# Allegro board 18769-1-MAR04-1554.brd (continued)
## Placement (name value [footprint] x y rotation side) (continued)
FC8970  SC12P50V2JN-DL-GP  [C402H22]  102.27 33.18 270 top
FC8971  SC12P50V2JN-DL-GP  [C402H22]  93.4 36.25 0 top
FC8972  SC12P50V2JN-DL-GP  [C402H22]  42.92 29.56 315 top
FC8973  SC12P50V2JN-DL-GP  [C402H22]  43.49 29.03 315 top
FP1  PTWO-CON8-11-GP  [FH52-8S-D5SH]  140.6 6.1 180 bottom
FSW1  SW-SLIDE3P-11-GP  [MSS3-Q-T-R]  172.66 24.46 270 top
G1801  GAP-OPEN  [CON2O-U]  117.2 28.58 0 top
GPU1  N17S-G1-A1-GP  [BGA595M23H83]  156.98 63.76 45 bottom
H5  HOLE233R142-GP-U1  [HOLE233R142]  7.8 44.5 0 top
H9  HOLE233R142-GP-U1  [HOLE233R142]  57.92 67.31 180 bottom
H10  HOLE233R142-GP-U1  [HOLE233R142]  57.92 43.01 180 bottom
H11  HOLE233R142-GP-U1  [HOLE233R142]  118.92 43.01 180 bottom
H12  HOLE233R142-GP-U1  [HOLE233R142]  118.92 67.31 180 bottom
H13  HOLE276R150-GP  [HOLE276R150]  138.13 68.48 0 bottom
H14  HOLE276R150-GP  [HOLE276R150]  166.74 43.33 180 bottom
H15  HOLE276R150-GP  [HOLE276R150]  166.04 79.47 180 bottom
H20  HOLE233R142-GP-U1  [HOLE233R142]  6.8 23.1 180 bottom
H22  HOLET237B213R142-GP  [HOLET237B213R142]  153.6 6.77 0 top
HALL1  AH9247-W-7-GP  [SOT23-2D8-312H56]  2.15 49.15 180 top
HDMI1  SKT-HDMI23-133-GP-U  [SKT-HDMI23-178125-2]  4.25 59.1 90 bottom
HS1  STFT237B158R128H48-GP  [STFT237B158R128H48]  193.44 22.05 180 bottom
HS2  STFT237B158R128H48-GP  [STFT237B158R128H48]  39.09 25.14 180 bottom
IO1  STM-CON30-6-GP  [20455-030E-12]  179.6 6 180 bottom
IO2  HRS-CONN40D-7-GP  [DF40C-40DP-D4V-51]  194.6 5.1 270 bottom
KB1  ACES-CON30-29-GP  [50699-03001-W01]  50.3 5.1 180 bottom
KBBL1  ACES-CON4-90-GP-U  [50698-00401-W01-U]  27.06 4.78 180 bottom
L7801  MHC1608S300QBP-GP  [L603H38]  159.99 67.96 229 top
L7901  MHC1608S300QBP-GP  [L603H38]  151.65 61.94 45 top
LCD1  IPEX-CON40-8-GP  [20879-040E-01]  46.6 81.1 0 bottom
LED1  LED-YW-5-GP  [LED3020-3P-19H44]  4 71.27 0 top
NOREF  -  []  39.4 81.73 0 top
NOREF#2  -  []  67.84 44 90 top
NOREF#3  -  []  138.11 89.19 0 top
NOREF#4  -  []  39.4 81.73 0 top
NOREF#5  -  []  20.55 45.33 90 top
NOREF#6  -  []  65.06 20.07 90 top
NOREF#7  -  []  76.26 30.37 0 top
NOREF#8  -  []  39.4 81.73 0 top
NOREF#9  -  []  14.85 8.28 0 top
NOREF#10  -  []  -166.49 -397.79 0 top
NOREF#11  -  []  39.09 22.63 90 top
NOREF#12  -  []  37.06 81.1 90 top
NOREF#13  -  []  -1.16 39.32 0 top
NOREF#14  -  []  38.8 78.82 0 top
NOREF#15  -  []  37.06 81.1 0 top
NOREF#16  -  [unnamed#2]  191.06 101.55 180 top
NOREF#17  -  []  65.06 29.67 0 top
NOREF#18  -  []  14.85 -1.52 90 top
NOREF#19  -  []  103.16 24.07 90 top
NOREF#20  -  []  56.49 82.12 90 top
NOREF#21  -  []  37.06 81.1 90 top
NOREF#22  -  []  103.16 20.07 90 top
NOREF#23  -  []  102 8.07 0 top
NOREF#24  -  []  18.84 44.83 0 top
NOREF#25  -  []  83.61 82.77 0 top
NOREF#26  -  []  174.54 74.78 0 top
NOREF#27  -  []  65.06 24.07 90 top
NOREF#28  -  []  204 81.94 0 top
NOREF#29  -  []  137.29 69.3 90 top
NOREF#30  -  []  38.8 78.82 0 top
NOREF#31  -  []  39.09 22.63 90 top
NOREF#32  -  []  39.4 78.07 0 top
NOREF#33  -  []  83.98 29.67 0 top
NOREF#34  -  []  196.47 10.12 90 top
NOREF#35  -  []  39.4 78.07 0 top
NOREF#36  *  [unnamed#2]  175.07 38.34 0 top
NOREF#37  *  [unnamed#2]  0.25 123.71 0 top
NOREF#38  -  []  37.01 78.74 90 top
NOREF#39  -  []  37.01 78.74 0 top
NOREF#40  -  []  38.16 81.73 0 top
NOREF#41  -  []  6.66 2.17 0 top
NOREF#42  -  []  18.84 44.83 0 top
NOREF#43  -  []  94.93 19.37 90 top
NOREF#44  -  []  115.2 68.26 90 top
NOREF#45  -  []  -0.83 28.22 0 top
NOREF#46  -  []  39.4 81.73 0 top
NOREF#47  -  []  37.06 81.1 0 top
NOREF#48  -  []  16.17 9.09 0 top
NOREF#49  -  []  114.39 99.23 180 top
NOREF#50  -  []  37.01 78.74 90 top
NOREF#51  -  []  37.06 81.1 0 top
NOREF#52  -  []  19.6 47.46 0 top
NOREF#53  -  []  193.2 1.3 0 top
NOREF#54  -  []  121.19 117.8 0 top
NOREF#55  -  []  38.8 78.82 0 top
NOREF#56  -  []  56.49 82.12 90 top
NOREF#57  -  []  45.93 27.81 90 top
NOREF#58  -  []  115.74 112.35 0 top
NOREF#59  -  []  67.84 43.35 0 top
NOREF#60  -  []  -2.81 37.24 0 top
NOREF#61  *  [unnamed#2]  163.12 86.33 0 top
NOREF#62  -  []  74.81 29.67 0 top
NOREF#63  -  []  38.16 81.73 0 top
NOREF#64  -  []  39.4 78.07 0 top
NOREF#65  -  []  101.34 19.89 0 top
NOREF#66  -  []  18.84 44.83 0 top
NOREF#67  -  []  39.83 5.94 90 top
NOREF#68  -  []  16.46 -2.32 90 top
NOREF#69  -  []  39.83 15.62 0 top
NOREF#70  -  []  65.06 23.27 90 top
NOREF#71  -  []  45.93 23.81 90 top
NOREF#72  -  []  18.84 44.83 90 top
NOREF#73  -  []  38.8 78.82 0 top
NOREF#74  -  []  83.98 23.27 90 top
NOREF#75  -  []  32.64 23.12 90 top
NOREF#76  -  []  137.29 68.8 90 top
NOREF#77  -  []  56.49 82.12 90 top
NOREF#78  -  []  38.09 78.07 0 top
NOREF#79  -  []  93.73 29.67 0 top
NOREF#80  -  []  39.4 78.07 0 top
NOREF#81  -  []  83.98 20.07 90 top
NOREF#82  -  [unnamed#2]  -3.68 12.32 0 top
NOREF#83  -  []  150.59 7.02 0 top
NOREF#84  *  [unnamed#2]  130.2 80.68 0 top
NOREF#85  -  []  188.8 52.8 0 top
NOREF#86  -  []  3.03 27.02 90 top
NOREF#87  -  []  81.95 42.9 90 top
NOREF#88  -  []  39.4 81.73 0 top
NOREF#89  -  []  45.52 5.94 90 top
NOREF#90  -  []  36.71 86.46 0 top
NOREF#91  -  []  38.8 78.82 90 top
NOREF#92  -  []  38.8 78.82 0 top
NOREF#93  *  [unnamed#2]  11.04 2.75 0 top
NOREF#94  -  []  56.88 23.11 90 top
NOREF#95  -  []  56.13 81.1 90 top
NOREF#96  -  []  38.8 78.82 0 top
NOREF#97  -  []  14.57 5.55 0 top
NOREF#98  -  []  37.01 78.74 90 top
NOREF#99  -  []  38.16 81.73 0 top
NOREF#100  -  []  114.11 19.37 90 top
NOREF#101  -  []  55.1 78.07 90 top
NOREF#102  -  []  19.6 47.46 0 top
NOREF#103  -  []  38.09 78.07 0 top
NOREF#104  -  []  39.4 78.07 0 top
NOREF#105  -  []  17.27 -1 90 top
NOREF#106  -  []  196.47 13.85 0 top
NOREF#107  -  []  89.87 19.38 90 top
NOREF#108  -  []  20.55 45.33 90 top
NOREF#109  -  []  51.77 19.38 90 top
NOREF#110  -  []  36.71 86.46 0 top
NOREF#111  -  [unnamed#2]  6.94 80.45 0 top
NOREF#112  -  [unnamed#2]  201.71 169.68 0 top
NOREF#113  -  [unnamed#2]  133.1 88.1 0 top
NOREF#114  *  [unnamed#2]  145.26 16.38 0 top
NOREF#115  -  []  71.1 41.21 0 top
NOREF#116  -  []  55.1 78.07 90 top
NOREF#117  -  []  81.95 42.9 90 top
NOREF#118  *  [unnamed#2]  93.45 10.56 0 top
NOREF#119  *  [unnamed#2]  182.39 35.94 0 top
NOREF#120  -  []  55.1 78.07 90 top
NOREF#121  -  []  57.13 34.12 0 top
NOREF#122  -  []  201.24 86.08 90 top
NOREF#123  -  []  95.57 70.9 0 top
NOREF#124  -  []  45.93 33.41 0 top
NOREF#125  -  []  -10.69 40.72 0 top
NOREF#126  -  []  63.24 19.89 0 top
NOREF#127  -  []  38.09 78.07 0 top
NOREF#128  -  []  130.47 26.52 0 top
NOREF#129  *  [unnamed#2]  50.89 15.86 0 top
NOREF#130  -  [unnamed#2]  199.79 55.24 180 top
NOREF#131  -  []  17.27 0.85 90 top
NOREF#132  -  []  55.89 51.26 0 top
NOREF#133  -  []  67.15 42.21 0 top
NOREF#134  -  []  39.4 78.07 0 top
NOREF#135  -  []  76.01 19.37 90 top
NOREF#136  *  [unnamed#2]  49.66 45.31 0 top
NOREF#137  *  [unnamed#2]  30.52 50.8 0 top
NOREF#138  -  []  103.16 23.27 90 top
NOREF#139  -  []  20.55 45.33 90 top
NOREF#140  *  [unnamed#2]  12.32 23.98 0 top
NOREF#141  -  [unnamed#2]  -2.05 128.95 0 top
NOREF#142  -  []  35.57 25.17 0 top
NOREF#143  *  [unnamed#2]  198.84 50.54 0 top
NOREF#144  -  []  37.01 78.74 0 top
NOREF#145  -  []  79.23 78.25 0 top
NOREF#146  -  []  38.8 78.82 90 top
NOREF#147  -  []  56.13 81.1 90 top
NOREF#148  -  []  55.68 33.41 0 top
NOREF#149  -  []  115.74 74.25 90 top
NOREF#150  -  []  150.29 6.95 0 top
NOREF#151  -  []  67.84 44 90 top
NOREF#152  -  []  18.84 44.83 90 top
NOREF#153  -  []  18.84 44.83 90 top
NOREF#154  -  []  14.85 -1.52 90 top
NOREF#155  -  []  35.57 25.17 0 top
NOREF#156  -  []  6.66 -2.32 90 top
NOREF#157  -  []  56.13 81.1 90 top
NOREF#158  -  []  45.93 27.01 90 top
NOREF#159  -  []  37.01 78.74 0 top
NOREF#160  -  []  37.06 81.1 90 top
NOREF#161  -  []  44.11 23.63 0 top
NOREF#162  -  []  39.4 81.73 0 top
NOREF#163  -  []  70.69 19.38 90 top
NOREF#164  -  []  19.6 47.46 0 top
NOREF#165  -  []  -74.36 -112.34 0 top
NOREF#166  -  []  38.8 78.82 90 top
NOREF#167  -  []  189.92 22.08 0 top
NOREF#168  -  []  19.34 -1.52 90 top
NOREF#169  -  []  83.98 24.07 90 top
NOREF#170  -  []  195.28 93.7 0 top
NOREF#171  -  []  193.44 19.54 90 top
NOREF#172  -  []  82.16 19.89 0 top
NOREF#173  -  []  36.66 16.69 0 top
NOREF#174  *  [unnamed#2]  183.82 5.74 0 top
NOREF#175  -  []  115.2 118.35 0 top
NOREF#176  -  []  13.73 -2.6 90 top
NOREF#177  *  [unnamed#2]  20.97 78.08 180 bottom
NOREF#178  -  []  60.79 57.2 180 bottom
NOREF#179  -  []  188.49 15.13 180 bottom
NOREF#180  *  [unnamed#2]  0.25 123.71 180 bottom
NOREF#181  *  [unnamed#2]  33.63 6.92 180 bottom
NOREF#182  -  []  194.1 28.96 180 bottom
NOREF#183  *  [unnamed#2]  167.92 54.21 180 bottom
NOREF#184  *  [unnamed#2]  170.91 38.49 180 bottom
NOREF#185  *  [unnamed#2]  61.92 38.33 180 bottom
NOREF#186  *  [unnamed#2]  58.87 80.47 180 bottom
NOREF#187  -  []  198.74 97.83 270 bottom
NOREF#188  -  []  179.29 66.86 180 bottom
NOREF#189  -  []  98.87 24.62 180 bottom
NOREF#190  *  [unnamed#2]  4.12 47.91 180 bottom
NOREF#191  -  []  60.59 26.95 180 bottom
NOREF#192  *  [unnamed#2]  108.75 80.68 180 bottom
NOREF#193  *  [unnamed#2]  192.93 11.64 180 bottom
NOREF#194  *  [unnamed#2]  144.74 18.74 180 bottom
NOREF#195  *  [unnamed#2]  165.04 86.44 180 bottom
NOREF#196  *  [unnamed#2]  198.84 50.54 180 bottom
PC44A1  SC100P50V2JN-3DLGP  [C402H22]  152.53 27.21 90 top
PC44A9  SC100P50V2JN-3DLGP  [C402H22]  154.63 26.24 270 top
PC44B1  SC100P50V2JN-3DLGP  [C402H22]  154.73 28.39 0 top
PC44B2  SCD1U25V2KX-1-DL-GP  [C402H22]  141.83 2.74 90 top
PC44B3  SC100P50V2JN-3DLGP  [C402H22]  153.91 28.38 0 top
PC44C1  SC100P50V2JN-3DLGP  [C402H22]  160.74 31.96 90 top
PC44C2  SC2D2U10V3KX-1DLGP-U  [C603H36]  157 27.67 0 top
PC44C3  SC10U25V3MX-5-GP  [C603H40]  157.85 31.14 90 top
PC1001  SC22U6D3V3MX-1-DL-GP  [C603H40]  77.1 60.33 90 top
PC1002  SC22U6D3V3MX-1-DL-GP  [C603H40]  79.48 71.89 180 bottom
PC1003  SC22U6D3V3MX-1-DL-GP  [C603H40]  84.02 54.68 270 top
PC1004  SC22U6D3V3MX-1-DL-GP  [C603H40]  86.95 55.95 90 top
PC1005  SC22U6D3V3MX-1-DL-GP  [C603H40]  81.11 52.43 90 top
PC1006  SC22U6D3V3MX-1-DL-GP  [C603H40]  81.08 54.92 90 top
PC1007  SC22U6D3V3MX-1-DL-GP  [C603H40]  89.93 55.97 270 top
PC1008  SC22U6D3V3MX-1-DL-GP  [C603H40]  89.93 52.16 270 top
PC1009  SC22U6D3V3MX-1-DL-GP  [C603H40]  92.98 58.34 90 top
PC1010  SC22U6D3V3MX-1-DL-GP  [C603H40]  93 53.38 90 top
PC1011  SC22U6D3V3MX-1-DL-GP  [C603H40]  89.98 58.51 270 top
PC1012  SC22U6D3V3MX-1-DL-GP  [C603H40]  84.02 58.24 270 top
PC1013  SC22U6D3V3MX-1-DL-GP  [C603H40]  84.01 55.86 270 top
PC1014  SC22U6D3V3MX-1-DL-GP  [C603H40]  87 58.49 90 top
PC1015  SC22U6D3V3MX-1-DL-GP  [C603H40]  89.93 57.24 270 top
PC1016  SC22U6D3V3MX-1-DL-GP  [C603H40]  93 57.14 90 top
PC1017  SC22U6D3V3MX-1-DL-GP  [C603H40]  80.3 51.19 90 top
PC1018  SC22U6D3V3MX-1-DL-GP  [C603H40]  73.85 72.78 180 bottom
PC1019  SC22U6D3V3MX-1-DL-GP  [C603H40]  72.58 72.78 180 bottom
PC1020  SC22U6D3V3MX-1-DL-GP  [C603H40]  93 55.92 90 top
PC1021  SC22U6D3V3MX-1-DL-GP  [C603H40]  86.98 57.27 90 top
PC1022  SC22U6D3V3MX-1-DL-GP  [C603H40]  84.8 72.85 180 bottom
PC1023  SC22U6D3V3MX-1-DL-GP  [C603H40]  84 52.27 270 top
PC1024  SC22U6D3V3MX-1-DL-GP  [C603H40]  89.93 53.43 270 top
PC1025  SC22U6D3V3MX-1-DL-GP  [C603H40]  89.93 54.7 270 top
PC1026  SC22U6D3V3MX-1-DL-GP  [C603H40]  84.02 57.05 270 top
PC1027  SC22U6D3V3MX-1-DL-GP  [C603H40]  84.02 53.49 270 top
PC1028  SC22U6D3V3MX-1-DL-GP  [C603H40]  86.95 54.68 90 top
PC1029  SC22U6D3V3MX-1-DL-GP  [C603H40]  93.23 60.25 90 top
PC1030  SC22U6D3V3MX-1-DL-GP  [C603H40]  81.11 53.7 90 top
PC1031  SC22U6D3V3MX-1-DL-GP  [C603H40]  81.08 58.48 90 top
PC1032  SC22U6D3V3MX-1-DL-GP  [C603H40]  86.95 53.41 90 top
PC1034  SC22U6D3V3MX-1-DL-GP  [C603H40]  81.08 57.28 90 top
PC1036  SC22U6D3V3MX-1-DL-GP  [C603H40]  81.08 56.1 90 top
PC1037  SC22U6D3V3MX-1-DL-GP  [C603H40]  71.48 63.6 90 top
PC1038  SC22U6D3V3MX-1-DL-GP  [C603H40]  77.31 49.94 270 top
PC1039  SC22U6D3V3MX-1-DL-GP  [C603H40]  61.73 54.54 90 top
PC1040  SC22U6D3V3MX-1-DL-GP  [C603H40]  77.31 57.15 270 top
PC1041  SC22U6D3V3MX-1-DL-GP  [C603H40]  74.31 55.91 90 top
PC1042  SC22U6D3V3MX-1-DL-GP  [C603H40]  77.31 53.52 270 top
PC1043  SC22U6D3V3MX-1-DL-GP  [C603H40]  64.45 60.3 180 top
PC1044  SC22U6D3V3MX-1-DL-GP  [C603H40]  77.31 52.33 270 top
PC1045  SC22U6D3V3MX-1-DL-GP  [C603H40]  77.31 58.33 270 top
PC1046  SC22U6D3V3MX-1-DL-GP  [C603H40]  77.31 54.79 270 top
PC1047  SC22U6D3V3MX-1-DL-GP  [C603H40]  62.93 57.26 0 top
PC1048  SC22U6D3V3MX-1-DL-GP  [C603H40]  74.31 54.64 90 top
PC1049  SC22U6D3V3MX-1-DL-GP  [C603H40]  68.21 60.61 180 top
PC1050  SC22U6D3V3MX-1-DL-GP  [C603H40]  79.9 49.82 90 top
PC1051  SC22U6D3V3MX-1-DL-GP  [C603H40]  64.2 57.26 0 top
PC1052  SC22U6D3V3MX-1-DL-GP  [C603H40]  66.99 60.3 180 top
PC1053  SC22U6D3V3MX-1-DL-GP  [C603H40]  63.18 60.3 180 top
PC1054  SC22U6D3V3MX-1-DL-GP  [C603H40]  73.61 61.08 180 top
PC1055  SC22U6D3V3MX-1-DL-GP  [C603H40]  61.91 60.3 180 top
PC1056  SC22U6D3V3MX-1-DL-GP  [C603H40]  61.68 57.23 0 top
PC1057  SC22U6D3V3MX-1-DL-GP  [C603H40]  54.8 48.05 180 bottom
PC1058  SC22U6D3V3MX-1-DL-GP  [C603H40]  74.31 58.43 90 top
PC1059  SC22U6D3V3MX-1-DL-GP  [C603H40]  65.72 60.3 180 top
PC1060  SC22U6D3V3MX-1-DL-GP  [C603H40]  77.31 55.97 270 top
PC1061  SC22U6D3V3MX-1-DL-GP  [C603H40]  74.31 50.83 90 top
PC1062  SC22U6D3V3MX-1-DL-GP  [C603H40]  74.31 52.1 90 top
PC1063  SC22U6D3V3MX-1-DL-GP  [C603H40]  65.52 54.64 270 top
PC1064  SC22U6D3V3MX-1-DL-GP  [C603H40]  65.39 57.26 0 top
PC1065  SC22U6D3V3MX-1-DL-GP  [C603H40]  66.59 57.26 0 top
PC1066  SC22U6D3V3MX-1-DL-GP  [C603H40]  74.31 53.37 90 top
PC1067  SC22U6D3V3MX-1-DL-GP  [C603H40]  74.31 57.18 90 top
PC1068  SC22U6D3V3MX-1-DL-GP  [C603H40]  70.52 61.65 270 top
PC1069  SC22U6D3V3MX-1-DL-GP  [C603H40]  77.28 51.14 270 top
PC1070  SC22U6D3V3MX-1-DL-GP  [C603H40]  53.61 48.05 180 bottom
PC1071  SC22U6D3V3MX-1-DL-GP  [C603H40]  96.02 54.15 270 top
PC1072  SC22U6D3V3MX-1-DL-GP  [C603H40]  98.29 58.09 0 top
PC1073  SC22U6D3V3MX-1-DL-GP  [C603H40]  96 58.88 270 top
PC1074  SC22U6D3V3MX-1-DL-GP  [C603H40]  99.68 73.02 180 bottom
PC1075  SC22U6D3V3MX-1-DL-GP  [C603H40]  96 55.33 270 top
PC1076  SC22U6D3V3MX-1-DL-GP  [C603H40]  96 56.49 270 top
PC1077  SC22U6D3V3MX-1-DL-GP  [C603H40]  96 57.71 270 top
PC1078  SC22U6D3V3MX-1-DL-GP  [C603H40]  98.49 73.02 180 bottom
PC1079  SC22U6D3V3MX-1-DL-GP  [C603H40]  78.27 71.91 180 bottom
PC1080  SC22U6D3V3MX-1-DL-GP  [C603H40]  86.95 52.14 90 top
PC1081  SC22U6D3V3MX-1-DL-GP  [C603H40]  89.04 49.78 270 top
PC1082  SC22U6D3V3MX-1-DL-GP  [C603H40]  93 52.15 90 top
PC1083  SC22U6D3V3MX-1-DL-GP  [C603H40]  93 54.65 90 top
PC1084  SC22U6D3V3MX-1-DL-GP  [C603H40]  91.65 49.88 90 top
PC4401  SCD1U25V2KX-1-DL-GP  [C402H22]  127.03 9.77 0 top
PC4402  SC10U25V5KX-DL-GP  [C805H58]  142.6 12.87 270 bottom
PC4404  SC10U25V5KX-DL-GP  [C805H58]  142.63 14.64 270 bottom
PC4405  SC10U25V5KX-DL-GP  [C805H58]  142.61 11.12 270 bottom
PC4406  SC10U25V5KX-DL-GP  [C805H58]  142.66 16.5 270 bottom
PC4415  SC4D7U25V5KX-DL-GP  [C805H54]  152.55 18.61 90 bottom
PC4416  SC1U25V3KX-1-DLGP  [C603H36]  153.87 18.57 180 top
PC4417  SC1U25V3KX-1-DLGP  [C603H36]  152.69 19.06 180 top
PC4419  SC1U25V3KX-1-DLGP  [C603H36]  155.07 17.3 180 top
PC4420  SCD1U25V2KX-1-DL-GP  [C402H22]  155.85 15.1 90 top
PC4422  SC4D7U6D3V3KX-DLGP  [C603H36]  155.86 15.86 270 bottom
PC4423  SCD22U25V3KX-DL-GP  [C603H36]  146.21 14.78 270 bottom
PC4424  SC1U25V3KX-1-DLGP  [C603H36]  145.03 11.08 90 top
PC4425  SC1U25V3KX-1-DLGP  [C603H36]  146.9 10.53 180 bottom
PC4429  SC4700P50V2KX-1DLGP  [C402H22]  122.84 9.4 180 bottom
PC4430  SC10P50V2JN-4DLGP  [C402H22]  155.61 11.74 270 bottom
PC4431  SCD01U50V2KX-1DLGP  [C402H22]  148.52 7.89 0 bottom
PC4432  SC1KP50V2KX-1DLGP  [C402H22]  138.6 5.31 270 top
PC4433  SC1KP50V2KX-1DLGP  [C402H22]  147.88 9.8 0 bottom
PC4435  SC1KP50V2KX-1DLGP  [C402H22]  138.9 20.63 270 top
PC4436  SCD22U25V3KX-DL-GP  [C603H36]  149.15 19.67 180 bottom
PC4439  SC1U25V3KX-1-DLGP  [C603H36]  142.62 11.37 270 top
PC4440  SC1U25V3KX-1-DLGP  [C603H36]  147.03 8.45 180 top
PC4441  SC10U25V5KX-DL-GP  [C805H58]  128.44 9.67 0 top
PC4442  SC10U25V5KX-DL-GP  [C805H58]  126.43 14.34 90 bottom
PC4443  SC10U25V5KX-DL-GP  [C805H58]  126.45 16.12 90 bottom
PC4444  SC10U25V5KX-DL-GP  [C805H58]  128.56 9.5 180 bottom
PC4449  SC10U25V5KX-DL-GP  [C805H58]  115.91 12.07 0 bottom
PC4450  SC10U25V5KX-DL-GP  [C805H58]  117.69 12.07 0 bottom
PC4451  SC1U25V3KX-1-DLGP  [C603H36]  145.84 9.22 180 top
PC4452  SC4D7U6D3V3KX-DLGP  [C603H36]  145.62 16.05 90 bottom
PC4461  SC10U25V5KX-DL-GP  [C805H58]  126.95 17.91 90 bottom
PC4462  SC10U25V5KX-DL-GP  [C805H58]  130.17 9.55 0 top
PC4465  SC22U25V5MX-5-GP  [C805H58]  132.06 9.52 180 bottom
PC4466  SC22U25V5MX-5-GP  [C805H58]  130.32 9.51 180 bottom
PC4467  SCD1U16V2KX-3DLGP  [C402H22]  149.08 21.98 90 top
PC4468  SCD1U16V2KX-3DLGP  [C402H22]  154.02 21.54 270 top
PC4469  SC1500P50V2KX-2-DL-GP  [C402H22]  173.64 9.25 180 top
PC4501  SCD1U25V2KX-1-DL-GP  [C402H22]  84.71 3 90 top
PC4502  SC4D7U25V5KX-DL-GP  [C805H54]  86.39 2.63 180 bottom
PC4503  SC4D7U25V5KX-DL-GP  [C805H54]  84.66 2.63 180 bottom
PC4506  SCD1U25V2KX-1-DL-GP  [C402H22]  91.84 4.8 90 top
PC4507  SC4D7U6D3V3KX-DLGP  [C603H36]  89.31 9.8 0 bottom
PC4508  SCD1U25V2KX-1-DL-GP  [C402H22]  84.45 9.34 0 top
PC4509  SC22U6D3V3MX-1-DL-GP  [C603H40]  96.4 12.46 0 bottom
PC4510  SC22U6D3V3MX-1-DL-GP  [C603H40]  95.2 12.45 0 bottom
PC4511  SC22U6D3V3MX-1-DL-GP  [C603H40]  93.18 12.45 0 bottom
PC4512  SC22U6D3V3MX-1-DL-GP  [C603H40]  91.99 12.45 0 bottom
PC4513  SCD1U25V2KX-1-DL-GP  [C402H22]  70.84 12.22 270 bottom
PC4526  SC1KP50V2KX-1DLGP  [C402H22]  86.66 11.65 0 bottom
PC4551  SC4D7U6D3V3KX-DLGP  [C603H36]  76.56 4.98 180 top
PC4552  SCD1U25V2KX-1-DL-GP  [C402H22]  77.61 8.82 90 bottom
PC4553  SCD1U25V2KX-1-DL-GP  [C402H22]  70.91 9.4 180 bottom
PC4554  SC10U25V5KX-DL-GP  [C805H58]  77.59 10.15 90 bottom
PC4555  SC10U25V5KX-DL-GP  [C805H58]  77.59 11.88 90 bottom
PC4556  SC22U6D3V3MX-1-DL-GP  [C603H40]  70.57 4.7 180 top
PC4557  SC22U6D3V3MX-1-DL-GP  [C603H40]  64.78 7.29 0 bottom
PC4558  SC22U6D3V3MX-1-DL-GP  [C603H40]  66.86 4.71 180 top
PC4559  SC22U6D3V3MX-1-DL-GP  [C603H40]  71.93 4.68 180 top
PC4560  SC22U6D3V3MX-1-DL-GP  [C603H40]  68.12 4.63 180 top
PC4561  SC22U6D3V3MX-1-DL-GP  [C603H40]  69.31 4.62 180 top
PC4562  SC2D2U10V3KX-1DLGP-U  [C603H36]  73.91 4.65 180 top
PC4563  SC1KP50V2KX-1DLGP  [C402H22]  78.29 2.25 0 top
PC4564  SCD1U25V2KX-1-DL-GP  [C402H22]  78.09 5 0 top
PC4565  SCD1U25V2KX-1-DL-GP  [C402H22]  64.7 4.25 180 top
PC4601  SC2200P50V2KX-2DLGP  [C402H22]  38.98 60.08 180 bottom
PC4602  SCD1U25V2KX-1-DL-GP  [C402H22]  47.42 67.24 0 top
PC4603  SCD1U25V2KX-1-DL-GP  [C402H22]  41.09 68.86 180 bottom
PC4604  SC330P50V2KX-3-DL-GP  [C402H22]  48.7 65.87 90 top
PC4605  SCD047U25V2KX-4-GP  [C402H22]  41.85 66.05 180 bottom
PC4606  SCD22U25V3KX-DL-GP  [C603H36]  44.71 66.95 0 top
PC4607  SC1U10V2KX-1DLGP  [C402H22]  46.06 69.52 0 bottom
PC4608  SCD022U16V2KX-3DLGP  [C402H22]  39.43 66.73 90 bottom
PC4610  SC33P50V2JN-3DLGP  [C402H22]  52.29 63.2 0 bottom
PC4611  SC2200P50V2KX-2DLGP  [C402H22]  42.66 68.56 180 bottom
PC4612  SC2200P50V2KX-2DLGP  [C402H22]  53.75 63.58 270 bottom
PC4613  SCD01U50V2KX-1DLGP  [C402H22]  41.82 64.42 0 bottom
PC4614  SC470P50V2KX-3DLGP  [C402H22]  53.56 61.93 270 bottom
PC4615  SCD01U50V2KX-1DLGP  [C402H22]  54.44 61.12 90 bottom
PC4616  SC1KP50V2KX-1DLGP  [C402H22]  39.58 64.02 90 bottom
PC4617  SC1KP50V2KX-1DLGP  [C402H22]  39.68 63.25 90 bottom
PC4618  SC470P50V2KX-3DLGP  [C402H22]  53.23 60.74 0 bottom
PC4619  SC1KP50V2KX-1DLGP  [C402H22]  53.17 59.09 180 bottom
PC4620  SCD01U50V2KX-1DLGP  [C402H22]  38.62 62.29 90 bottom
PC4621  SC680P50V2KX-2DLGP  [C402H22]  38.62 61.4 270 bottom
PC4622  SCD01U50V2KX-1DLGP  [C402H22]  48.7 65.05 270 top
PC4623  SC2200P50V2KX-2DLGP  [C402H22]  49.03 59.49 270 bottom
PC4624  SC33P50V2JN-3DLGP  [C402H22]  40.29 59.48 90 bottom
PC4625  SCD022U16V2KX-3DLGP  [C402H22]  49.92 62.43 90 top
PC4626  SCD022U16V2KX-3DLGP  [C402H22]  49.55 58.16 0 top
PC4628  SCD022U16V2KX-3DLGP  [C402H22]  52.64 57.36 180 bottom
PC4629  SC330P50V2KX-3-DL-GP  [C402H22]  44.41 64.78 270 top
PC4630  SCD047U25V2KX-4-GP  [C402H22]  50.69 57.71 90 bottom
PC4631  SCD1U25V2KX-1-DL-GP  [C402H22]  39.79 61.12 270 top
PC4632  SC2200P50V2KX-2DLGP  [C402H22]  42.05 62.36 180 top
PC4633  SCD1U25V2KX-1-DL-GP  [C402H22]  50.63 63.28 90 top
PC4634  SCD047U25V2KX-4-GP  [C402H22]  41.62 60.2 90 top
PC4635  SCD022U16V2KX-3DLGP  [C402H22]  41.62 59.39 90 top
PC4637  SCD01U50V2KX-1DLGP  [C402H22]  43.88 60.25 270 bottom
PC4638  SC330P50V2KX-3-DL-GP  [C402H22]  47.66 62.82 180 top
PC4639  SC33P50V2JN-3DLGP  [C402H22]  46.85 62.77 180 top
PC4640  SC2200P50V2KX-2DLGP  [C402H22]  45.63 63.2 90 top
PC4641  SC330P50V2KX-3-DL-GP  [C402H22]  47.08 58.25 180 bottom
PC4642  SC1KP50V2KX-1DLGP  [C402H22]  43.9 58.68 270 bottom
PC4643  SC1KP50V2KX-1DLGP  [C402H22]  45.94 58.6 90 bottom
PC4644  SCD01U50V2KX-1DLGP  [C402H22]  45.02 59.42 90 top
PC4651  SC1KP50V2KX-1DLGP  [C402H22]  53.76 62.8 270 bottom
PC4652  SCD022U16V2KX-3DLGP  [C402H22]  42.3 58.36 90 top
PC4653  SCD047U25V2KX-4-GP  [C402H22]  51.88 57.36 180 bottom
PC4654  SCD01U25V2KX-3DLGP  [C402H22]  53.43 57.36 180 bottom
PC4702  SC10U25V3MX-5-GP  [C603H40]  76.81 84.15 0 top
PC4703  SC10U25V3MX-5-GP  [C603H40]  73.82 83.57 180 bottom
PC4704  SC10U25V3MX-5-GP  [C603H40]  95.36 84.34 0 top
PC4705  SC10U25V3MX-5-GP  [C603H40]  75.04 83.58 180 bottom
PC4708  SCD22U25V3KX-DL-GP  [C603H36]  72.27 87.09 270 top
PC4709  SC2D2U6D3V2MX-DL-GP  [C402H22]  68.14 86.41 0 top
PC4710  SC1KP50V2KX-1DLGP  [C402H22]  68.29 81.59 180 top
PC4711  SCD22U25V3KX-DL-GP  [C603H36]  93.64 88.12 270 top
PC4712  SC2D2U6D3V2MX-DL-GP  [C402H22]  86.45 87.4 90 bottom
PC4713  SC1KP50V2KX-1DLGP  [C402H22]  92.29 81.72 180 top
PC4714  SC10U25V3MX-5-GP  [C603H40]  94.04 84.38 180 bottom
PC4715  SC10U25V3MX-5-GP  [C603H40]  95.25 84.39 180 bottom
PC4716  SC10U25V3MX-5-GP  [C603H40]  94.03 84.36 0 top
PC4717  SC10U25V3MX-5-GP  [C603H40]  78.01 84.15 0 top
PC4766  SC2D2U6D3V2MX-DL-GP  [C402H22]  86.83 84.57 180 bottom
PC4777  SC2D2U6D3V2MX-DL-GP  [C402H22]  67.45 85.18 90 top
PC4801  SC10U25V3MX-5-GP  [C603H40]  41.36 55.94 270 bottom
PC4802  SC10U25V3MX-5-GP  [C603H40]  41.45 55.83 90 top
PC4803  SC10U25V3MX-5-GP  [C603H40]  41.36 54.67 270 bottom
PC4804  SC10U25V3MX-5-GP  [C603H40]  41.44 54.66 90 top
PC4806  SC1KP50V2KX-1DLGP  [C402H22]  46.06 53.14 180 top
PC4807  SCD22U25V3KX-DL-GP  [C603H36]  44.62 47.45 180 top
PC4808  SC2D2U6D3V2MX-DL-GP  [C402H22]  37.98 46.91 180 bottom
PC4866  SC2D2U6D3V2MX-DL-GP  [C402H22]  40.9 46.9 180 bottom
PC5001  SC2D2U10V3KX-1DLGP-U  [C603H36]  101.82 86.9 180 top
PC5002  SC10U25V5KX-DL-GP  [C805H58]  100.25 83.44 270 bottom
PC5003  SC10U25V5KX-DL-GP  [C805H58]  97.23 81.38 180 bottom
PC5004  SCD1U25V2KX-1-DL-GP  [C402H22]  101.31 84.21 90 top
PC5005  SCD22U25V3KX-DL-GP  [C603H36]  106.01 85.5 0 top
PC5101  SC10U25V5KX-DL-GP  [C805H58]  35.79 36.19 180 bottom
PC5102  SC4D7U6D3V3KX-DLGP  [C603H36]  27.64 30.26 180 bottom
PC5103  SC2D2U6D3V2MX-DL-GP  [C402H22]  33.62 39.32 180 top
PC5104  SC2D2U6D3V2MX-DL-GP  [C402H22]  31.97 44.63 270 bottom
PC5105  SC10U25V5KX-DL-GP  [C805H58]  37.6 36.16 180 bottom
PC5106  SC22U6D3V3MX-1-DL-GP  [C603H40]  42.98 43.91 180 top
PC5107  SC22U6D3V3MX-1-DL-GP  [C603H40]  47.42 42.69 270 bottom
PC5108  SCD1U25V2KX-1-DL-GP  [C402H22]  34.76 39.68 270 top
PC5109  SC22U6D3V3MX-1-DL-GP  [C603H40]  47.42 43.96 270 bottom
PC5110  SCD1U25V2KX-1-DL-GP  [C402H22]  36.34 38.1 90 top
PC5111  SC10U6D3V3MX-DL-GP  [C603H36]  32.37 37.07 180 bottom
PC5112  SC10U6D3V3MX-DL-GP  [C603H36]  31.17 37.07 180 bottom
PC5113  SC22U6D3V3MX-1-DL-GP  [C603H40]  44.25 43.91 180 top
PC5114  SCD1U25V2KX-1-DL-GP  [C402H22]  32.45 39.36 90 top
PC5115  SC1500P50V2KX-2-DL-GP  [C402H22]  33.17 42.8 180 top
PC5151  SC1U10V2KX-1DLGP  [C402H22]  28.8 43.73 90 bottom
PC5152  SC68P50V2JN-1DLGP  [C402H22]  36.82 31.83 180 top
PC5153  SC22U6D3V5MX-2DLGP  [C805H54]  36.49 31.52 0 bottom
PC5154  SC10U6D3V3MX-DL-GP  [C603H36]  37.99 32.08 0 bottom
PC5155  SC10U6D3V3MX-DL-GP  [C603H36]  31.46 35.27 90 bottom
PC5156  SCD1U25V2KX-1-DL-GP  [C402H22]  27.62 34.98 0 bottom
PC5201  SC22U6D3V3MX-1-DL-GP  [C603H40]  114.66 87.6 0 bottom
PC5202  SC4D7U25V5KX-DL-GP  [C805H54]  120.81 87.28 90 bottom
PC5203  SC22U6D3V3MX-1-DL-GP  [C603H40]  110.92 87.65 0 bottom
PC5204  SCD1U25V2KX-1-DL-GP  [C402H22]  124.62 82.58 180 top
PC5205  SC22U6D3V3MX-1-DL-GP  [C603H40]  115.84 87.59 0 bottom
PC5206  SC22U6D3V3MX-1-DL-GP  [C603H40]  113.48 87.6 0 bottom
PC5207  SC22U6D3V3MX-1-DL-GP  [C603H40]  109.75 87.65 0 bottom
PC5208  SCD1U25V2KX-1-DL-GP  [C402H22]  131.91 85.78 0 bottom
PC5209  SC10U25V5KX-DL-GP  [C805H58]  130.57 86.04 0 bottom
PC5210  SC10U25V5KX-DL-GP  [C805H58]  128.8 86.04 0 bottom
PC5212  SC220P50V2KX-3DLGP  [C402H22]  126.99 86.93 90 bottom
PC5213  SCD01U25V2KX-3DLGP  [C402H22]  122.68 87.17 0 bottom
PC5214  SCD1U16V2KX-3DLGP  [C402H22]  124.24 87.17 0 bottom
PC5301  SC22U6D3V3MX-1-DL-GP  [C603H40]  23.74 48.29 0 bottom
PC5302  SC22U6D3V3MX-1-DL-GP  [C603H40]  32.26 48.75 270 bottom
PC5303  SC22U6D3V3MX-1-DL-GP  [C603H40]  32.26 47.52 270 bottom
PC5305  SC22P50V2JN-9-GP  [C402H22]  28.39 44.86 180 bottom
PC5307  SC1U10V2KX-1DLGP  [C402H22]  25.1 47.38 0 top
PC8551  SC10U25V5KX-DL-GP  [C805H58]  131.73 37.73 0 bottom
PC8552  SC10U25V5KX-DL-GP  [C805H58]  157.21 35.29 270 bottom
PC8553  SC10U25V5KX-DL-GP  [C805H58]  157.22 33.54 270 bottom
PC8554  SCD1U25V2KX-1-DL-GP  [C402H22]  142.41 24.21 270 top
PC8555  SC2D2U6D3V2MX-DL-GP  [C402H22]  144.07 32.41 0 bottom
PC8556  SCD1U25V2KX-1-DL-GP  [C402H22]  149.05 30.76 90 bottom
PC8557  SCD01U50V2KX-1DLGP  [C402H22]  146.51 28.79 270 top
PC8558  SC22U6D3V5MX-2DLGP  [C805H54]  129.1 44.82 90 bottom
PC8559  SC22U6D3V5MX-2DLGP  [C805H54]  129.1 46.6 90 bottom
PC8560  SC1KP50V2KX-1DLGP  [C402H22]  146.54 27.25 90 top
PC8561  SC33P50V2JN-3DLGP  [C402H22]  141.21 28.83 270 top
PC8562  SCD1U25V2KX-1-DL-GP  [C402H22]  144.02 28.48 0 top
PC8563  SC33P50V2JN-3DLGP  [C402H22]  143.57 25.78 90 bottom
PC8564  SC33P50V2JN-3DLGP  [C402H22]  146.45 23.52 270 bottom
PC8565  SC4700P50V2KX-1DLGP  [C402H22]  146.5 24.11 270 top
PC8566  SC33P50V2JN-3DLGP  [C402H22]  141.24 27.11 0 top
PC8567  SCD01U50V2KX-1DLGP  [C402H22]  147.28 24.89 270 top
PC8568  SC10U25V5KX-DL-GP  [C805H58]  133.6 37.74 0 bottom
PC8569  SCD1U25V2KX-1-DL-GP  [C402H22]  141.95 30.83 270 bottom
PC8570  SC22U6D3V5MX-2DLGP  [C805H54]  155.39 38.99 180 bottom
PC8571  SC22U6D3V5MX-2DLGP  [C805H54]  129.07 43.08 90 bottom
PC8601  SC10U6D3V3MX-DL-GP  [C603H36]  132.09 80.41 0 bottom
PC8602  SC330P50V2KX-3-DL-GP  [C402H22]  175.25 35.97 90 top
PC8607  SCD1U16V2KX-3DLGP  [C402H22]  136.13 78.33 180 bottom
PC8609  SCD01U50V2KX-1DLGP  [C402H22]  185.23 33.79 270 bottom
PC8610  SC10U25V5KX-DL-GP  [C805H58]  183.55 34.43 180 bottom
PC8611  SC22U6D3V3MX-1-DL-GP  [C603H40]  183.39 43.61 270 bottom
PC8612  SCD22U10V2KX-2-GP  [C402H22]  131.81 62.45 270 top
PC8613  SC22U6D3V3MX-1-DL-GP  [C603H40]  175.14 43.79 90 bottom
PC8614  SCD1U16V2KX-3DLGP  [C402H22]  183.36 44.58 270 bottom
PC8615  SC10U25V5KX-DL-GP  [C805H58]  181.75 34.7 180 bottom
PC8616  SCD1U16V2KX-3DLGP  [C402H22]  178.35 34.21 90 top
PC8617  SC2D2U10V3KX-1DLGP-U  [C603H36]  174.04 37.21 90 bottom
PC8618  SC1U10V2KX-1DLGP  [C402H22]  177.69 37.05 90 top
PC8619  SCD1U25V2KX-1-DL-GP  [C402H22]  183.18 38.51 90 bottom
PC8620  SC22U6D3V3MX-1-DL-GP  [C603H40]  183.42 42.4 270 bottom
PC8621  SC22U6D3V3MX-1-DL-GP  [C603H40]  175.13 45.08 90 bottom
PC8622  SC10U6D3V3MX-DL-GP  [C603H36]  130.92 80.42 0 bottom
PC8623  SC1U10V2KX-1DLGP  [C402H22]  129.93 80.59 0 bottom
PC8624  SC22P50V2JN-9-GP  [C402H22]  133.61 77.7 90 bottom
PC8625  SC10U6D3V3MX-DL-GP  [C603H36]  140.11 82.05 0 bottom
PC8626  SC10U6D3V3MX-DL-GP  [C603H36]  138.88 82.08 0 bottom
PC8627  SC10U6D3V3MX-DL-GP  [C603H36]  142.43 87.83 180 top
PC8628  SC22U6D3V3MX-1-DL-GP  [C603H40]  137.63 88.27 0 bottom
PC8629  SC1U10V2KX-1DLGP  [C402H22]  141.43 87.75 180 top
PC8630  SC10U6D3V3MX-DL-GP  [C603H36]  143.71 87.82 180 top
PC8631  SC22U6D3V3MX-1-DL-GP  [C603H40]  136.44 87.91 0 bottom
PC8632  SC22P50V2JN-9-GP  [C402H22]  139.57 88.27 270 bottom
PD44A1  L1SS355T1G-GP  [SOD323AKH44]  157.06 27.31 90 bottom
PD44B1  L1SS355T1G-GP  [SOD323AKH44]  161.01 4.3 90 top
PD4401  BAT54C-12-GP  [SOT-23-9H44]  156.68 19.74 0 bottom
PD4403  L1SS355T1G-GP  [SOD323AKH44]  144.19 21.79 270 bottom
PD4407  RB520S30-GP  [SOD523AKH26]  157.17 20.76 270 top
PD4408  BAT54C-12-GP  [SOT-23-9H44]  156.61 22.96 0 top
PD5101  AZ4024-01L-R7G-GP  [SOD323AKH40]  33.87 36.38 0 bottom
PG4401  GAP-CLOSE-PWR-3-GP  [GAP-CLOSE-PWR-3]  28.92 68.18 270 top
PG4402  GAP-CLOSE-PWR-3-GP  [GAP-CLOSE-PWR-3]  31.51 68.15 270 top
PG4405  GAP-CLOSE-PWR-3-GP  [GAP-CLOSE-PWR-3]  122.51 9.72 90 top
PG4406  GAP-CLOSE-PWR-3-GP  [GAP-CLOSE-PWR-3]  120.68 9.68 90 top
PG4408  GAP-CLOSE-PWR-3-GP  [GAP-CLOSE-PWR-3]  143.39 4.61 0 top
PG4530  GAP-CLOSE-PWR-3-GP  [GAP-CLOSE-PWR-3]  90.65 11.74 0 bottom
PG4532  GAP-CLOSE-PWR-3-GP  [GAP-CLOSE-PWR-3]  88.19 10.15 270 bottom
PG4562  GAP-CLOSE-PWR-3-GP  [GAP-CLOSE-PWR-3]  72.75 1.99 180 top
PG4565  GAP-CLOSE-PWR-3-GP  [GAP-CLOSE-PWR-3]  75.79 2.99 270 top
PG4601  GAP-CLOSE-PWR-3-GP  [GAP-CLOSE-PWR-3]  50.36 69.17 180 top
PG4708  GAP-CLOSE-PWR-3-GP  [GAP-CLOSE-PWR-3]  69.01 77.58 0 bottom
PG4709  GAP-CLOSE-PWR-3-GP  [GAP-CLOSE-PWR-3]  71.41 77.55 180 bottom
PG4713  GAP-CLOSE-PWR-3-GP  [GAP-CLOSE-PWR-3]  89.75 77.91 180 bottom
PG4715  GAP-CLOSE-PWR-3-GP  [GAP-CLOSE-PWR-3]  87.21 77.91 0 bottom
PG4807  GAP-CLOSE-PWR-3-GP  [GAP-CLOSE-PWR-3]  47.43 48.24 180 bottom
PG4808  GAP-CLOSE-PWR-3-GP  [GAP-CLOSE-PWR-3]  49.8 48.29 0 bottom
PG5001  GAP-CLOSE-PWR-3-GP  [GAP-CLOSE-PWR-3]  102.31 77.21 90 bottom
PG5011  GAP-CLOSE-PWR-3-GP  [GAP-CLOSE-PWR-3]  102.23 79.42 270 bottom
PG5104  GAP-CLOSE-PWR-3-GP  [GAP-CLOSE-PWR-3]  44.67 37.59 90 bottom
PG5105  GAP-CLOSE-PWR-3-GP  [GAP-CLOSE-PWR-3]  47.12 37.59 270 top
PG5106  GAP-CLOSE-PWR-3-GP  [GAP-CLOSE-PWR-3]  47.88 37.59 270 top
PG5107  GAP-CLOSE-PWR-3-GP  [GAP-CLOSE-PWR-3]  45.6 37.59 270 bottom
PG5108  GAP-CLOSE-PWR-3-GP  [GAP-CLOSE-PWR-3]  46.36 37.59 270 bottom
PG5109  GAP-CLOSE-PWR-3-GP  [GAP-CLOSE-PWR-3]  47.12 37.59 270 bottom
PG5110  GAP-CLOSE-PWR-3-GP  [GAP-CLOSE-PWR-3]  45.6 37.59 270 top
PG5111  GAP-CLOSE-PWR-3-GP  [GAP-CLOSE-PWR-3]  29.53 37.48 0 bottom
PG5112  GAP-CLOSE-PWR-3-GP  [GAP-CLOSE-PWR-3]  47.88 37.59 270 bottom
PG5113  GAP-CLOSE-PWR-3-GP  [GAP-CLOSE-PWR-3]  29.53 38.24 0 bottom
PG5114  GAP-CLOSE-PWR-3-GP  [GAP-CLOSE-PWR-3]  46.36 37.59 270 top
PG5115  GAP-CLOSE-PWR-3-GP  [GAP-CLOSE-PWR-3]  33.19 36.96 90 top
PG5116  GAP-CLOSE-PWR-3-GP  [GAP-CLOSE-PWR-3]  33.95 36.96 90 top
PG5152  0R5J-5-GP  [R805H24]  42.79 31.36 270 top
PG5201  GAP-CLOSE-PWR-3-GP  [GAP-CLOSE-PWR-3]  130.14 83.46 90 bottom
PG5202  GAP-CLOSE-PWR-3-GP  [GAP-CLOSE-PWR-3]  130.9 83.46 90 bottom
PG5203  GAP-CLOSE-PWR-3-GP  [GAP-CLOSE-PWR-3]  129.38 83.46 90 bottom
PG5210  GAP-CLOSE-PWR-3-GP  [GAP-CLOSE-PWR-3]  116.42 87.15 0 top
PG5302  GAP-CLOSE-PWR-3-GP  [GAP-CLOSE-PWR-3]  22.35 46.39 270 bottom
PG5303  GAP-CLOSE-PWR-3-GP  [GAP-CLOSE-PWR-3]  23.12 46.39 270 bottom
PG8601  GAP-CLOSE-PWR-3-GP  [GAP-CLOSE-PWR-3]  128.78 80.34 0 bottom
PG8602  GAP-CLOSE-PWR-3-GP  [GAP-CLOSE-PWR-3]  128.78 79.58 0 bottom
PG8603  GAP-CLOSE-PWR-3-GP  [GAP-CLOSE-PWR-3]  138.69 79.93 90 bottom
PG8604  GAP-CLOSE-PWR-3-GP  [GAP-CLOSE-PWR-3]  139.45 79.93 90 bottom
PG8605  GAP-CLOSE-PWR-3-GP  [GAP-CLOSE-PWR-3]  145.04 87.61 180 top
PG8606  GAP-CLOSE-PWR-3-GP  [GAP-CLOSE-PWR-3]  145.04 86.85 180 top
PG8607  GAP-CLOSE-PWR-3-GP  [GAP-CLOSE-PWR-3]  135.37 87.43 90 bottom
PG8608  GAP-CLOSE-PWR-3-GP  [GAP-CLOSE-PWR-3]  134.61 87.43 90 bottom
PG8609  GAP-CLOSE-PWR-3-GP  [GAP-CLOSE-PWR-3]  176.81 45.01 90 bottom
PG8610  GAP-CLOSE-PWR-3-GP  [GAP-CLOSE-PWR-3]  177.57 45.01 90 bottom
PG8611  GAP-CLOSE-PWR-3-GP  [GAP-CLOSE-PWR-3]  178.33 45.01 90 bottom
PG8612  GAP-CLOSE-PWR-3-GP  [GAP-CLOSE-PWR-3]  179.09 45.01 90 bottom
PG8613  GAP-CLOSE-PWR-3-GP  [GAP-CLOSE-PWR-3]  179.47 41.93 270 bottom
PG8614  GAP-CLOSE-PWR-3-GP  [GAP-CLOSE-PWR-3]  185.27 34.73 180 bottom
PG8615  GAP-CLOSE-PWR-3-GP  [GAP-CLOSE-PWR-3]  185.27 35.49 180 bottom
PG8616  GAP-CLOSE-PWR-3-GP  [GAP-CLOSE-PWR-3]  185.27 36.25 180 bottom
PG8617  GAP-CLOSE-PWR-3-GP  [GAP-CLOSE-PWR-3]  185.27 37.01 180 bottom
PG8618  GAP-CLOSE-PWR-3-GP  [GAP-CLOSE-PWR-3]  182.14 45.01 90 bottom
PG8619  GAP-CLOSE-PWR-3-GP  [GAP-CLOSE-PWR-3]  181.38 45.01 90 bottom
PG8620  GAP-CLOSE-PWR-3-GP  [GAP-CLOSE-PWR-3]  180.62 45.01 90 bottom
PG8621  GAP-CLOSE-PWR-3-GP  [GAP-CLOSE-PWR-3]  179.85 45.01 90 bottom
PL4401  IND-2D2UH-447-GP  [L109100-2430-UH119]  135.09 16.31 90 bottom
PL4501  IND-1D5UH-23-GP-U  [L7066-1830-UH119]  93.52 7.16 0 bottom
PL4551  IND-1D5UH-23-GP-U  [L7066-1830-UH119]  69.72 5.1 90 bottom
PL4701  IND-D15UH-33-GP  [L7366-1830H119]  70.22 77.59 270 bottom
PL4702  IND-D15UH-33-GP  [L7366-1830H119]  88.52 77.99 90 bottom
PL4703  HCB2012KF-800T50-GP-U  [L20125H42]  74.04 87.06 180 bottom
PL4704  HCB2012KF-800T50-GP-U  [L20125H42]  75.66 87.06 180 bottom
PL4801  IND-D15UH-33-GP  [L7366-1830H119]  48.62 48.19 270 bottom
PL4802  HCB2012KF-800T50-GP-U  [L20125H42]  39.25 57.02 180 bottom
PL4803  HCB2012KF-800T50-GP-U  [L20125H42]  37.61 57.52 180 bottom
PL5001  IND-D47UH-22-GP-U  [L7066-1830-UH119]  102.08 78.35 180 bottom
PL5101  IND-1D5UH-23-GP-U  [L7066-1830-UH119]  40.19 42.53 270 bottom
PL5201  COIL-1UH-34-GP-U1  [L7066-1830-UH119]  117.93 82.84 90 bottom
PL5301  IND-1UH-300-GP  [L2520-D620H48]  29.21 48.27 270 bottom
PL8551  IND-D15UH-33-GP  [L7366-1830H119]  138.93 43.12 0 bottom
PL8552  IND-D15UH-33-GP  [L7366-1830H119]  150.9 42.78 0 bottom
PL8601  IND-1UH-300-GP  [L2520-D620H48]  136.92 80.85 0 bottom
PL8602  IND-1UH-300-GP  [L2520-D620H48]  135.83 84.99 0 bottom
PL8603  COIL-1UH-73-GP  [L4947-1115H119]  179.5 41.22 0 bottom
PQ44A1  2N7002KDW-1-GP  [SOT-363H44]  160.09 27.92 270 top
PQ44B1  2N7002KDW-1-GP  [SOT-363H44]  145.8 2.8 90 top
PQ4402  2N7002K-2-GP  [SOT23DGS2D4H44]  148.93 22.92 180 bottom
PQ4405  2N7002KDW-1-GP  [SOT-363H44]  153.62 23.37 180 top
PQ4408  MMBT3906-3-GP  [SOT23CBE2D4H44]  141.03 24.01 90 bottom
PQ4415  2N7002KDW-1-GP  [SOT-363H44]  140.87 4.58 90 top
PQ4416  2N7002KDW-1-GP  [SOT-363H44]  153.56 22.11 180 bottom
PQ4417  2N7002K-2-GP  [SOT23DGS2D4H44]  150.2 27.23 90 bottom
PQ4418  2N7002KDW-1-GP  [SOT-363H44]  149.38 20.11 0 top
PQ4451  SM2421PSANC-TRG-GP  [SOT23DGS2D4H48]  165.53 35.83 270 bottom
PQ4452  2N7002KDW-1-GP  [SOT-363H44]  135.2 2.39 90 top
PR44A1  249KR2F-GP  [R402H16]  155.58 27.04 90 top
PR44A2  365KR2F-GP  [R402H16]  151.24 27.2 0 top
PR44A3  107KR2F-GP  [R402H16]  152.48 26.43 90 top
PR44A4  10KR2F-2-GP  [R402H16]  162.91 29.67 270 top
PR44A5  0R2J-2-GP  [R402H16]  159.69 21.97 0 top
PR44A6  205KR2F-GP  [R402H16]  134.98 56.24 270 bottom
PR44B1  150KR2F-L-GP  [R402H16]  153.09 28.38 0 top
PR44B2  200KR2F-L-GP  [R402H16]  154.64 29.96 0 top
PR44B3  133KR2F-GP  [R402H16]  155.53 28.33 0 top
PR44B4  10KR2F-2-GP  [R402H16]  151.4 31.35 0 bottom
PR44B5  100KR2F-L3-GP  [R402H16]  146.45 4.46 90 top
PR44B6  100KR2F-L3-GP  [R402H16]  139.98 2.91 90 top
PR44B7  165KR2F-GP  [R402H16]  151.15 29.18 180 top
PR44C1  10KR2F-2-GP  [R402H16]  158.09 32.53 0 top
PR44C2  16K9R2F-GP  [R402H16]  158 28.08 180 top
PR44C3  10KR2F-2-GP  [R402H16]  160.03 30.03 90 top
PR44C4  100KR2F-L3-GP  [R402H16]  159.56 32.24 0 top
PR44C5  0R2J-2-GP  [R402H16]  156.61 29.55 270 top
PR44C6  0R2J-2-GP  [R402H16]  164.47 30.27 180 top
PR44C7  13K3R2F-L1-GP  [R402H16]  157.32 32.52 180 top
PR2455  150KR2F-L-GP  [R402H16]  35.14 16.92 90 bottom
PR4401  D01R6F-1-GP  [R1206H38]  30.16 69.3 90 top
PR4402  2D2R3F-L-GP  [R603H24]  150.34 20.13 0 bottom
PR4403  2D2R5J-1-GP  [R805H24]  155.8 17.31 90 bottom
PR4404  402KR2F-GP  [R402H16]  158.73 22.36 0 top
PR4405  4D7R2F-GP  [R402H16]  146.76 17.48 270 bottom
PR4406  100KR2F-L3-GP  [R402H16]  152.75 15.53 225 top
PR4407  D005RL3720F-1-GP  [RL3720H40]  121.61 11.93 270 top
PR4408  2D2R3F-L-GP  [R603H24]  146.21 13.6 90 bottom
PR4409  100KR2F-L3-GP  [R402H16]  155.09 10.96 90 bottom
PR4410  93K1R2F-L-GP  [R402H16]  151.74 12.62 90 top
PR4411  499R2F-2-GP  [R402H16]  151.76 10.91 270 bottom
PR4413  13K7R2F-GP  [R402H16]  150.09 12.38 270 top
PR4416  2D2R5J-1-GP  [R805H24]  139.79 19.11 135 top
PR4417  100KR2F-L3-GP  [R402H16]  153.17 14.11 270 top
PR4422  1R2F-GP  [R402H16]  153.37 19.85 90 bottom
PR4424  1R2F-GP  [R402H16]  145.47 10.7 90 bottom
PR4425  1R2F-GP  [R402H16]  145.5 9.87 90 bottom
PR4426  196KR2F-GP  [R402H16]  156.66 13.25 90 top
PR4429  100KR2F-L3-GP  [R402H16]  155.62 11.84 180 top
PR4435  100KR2F-L3-GP  [R402H16]  155.66 12.51 90 bottom
PR4436  1MR2J-1-GP  [R402H16]  140.46 24.49 90 top
PR4437  100KR2F-L3-GP  [R402H16]  139.27 24.15 180 top
PR4438  100KR2F-L3-GP  [R402H16]  152.41 21.54 270 top
PR4439  680KR2F-GP  [R402H16]  142.14 25.4 0 bottom
PR4440  -  [0R0402-PAD]  132.44 2.8 0 top
PR4441  0R2F-1-GP  [R402H16]  133.24 2.8 0 top
PR4442  100KR2F-L3-GP  [R402H16]  155.69 14.89 270 bottom
PR4443  10KR2F-2-GP  [R402H16]  151.04 23 0 top
PR4459  0R2J-L-GP  [R402H15]  148.97 18.26 270 top
PR4460  10KR2F-2-GP  [R402H16]  146.89 21.28 180 top
PR4461  100KR2F-L3-GP  [R402H16]  151.29 18.58 90 top
PR4462  100KR2F-L3-GP  [R402H16]  145.4 18.86 0 top
PR4463  0R2J-L-GP  [R402H15]  149.62 25.15 0 top
PR4464  100KR2F-L3-GP  [R402H16]  170.43 11.34 270 top
PR4465  -  [0R0402-PAD]  172.99 10.84 270 top
PR4466  100KR2F-L3-GP  [R402H16]  172.87 9.63 180 top
PR4467  10KR2F-2-GP  [R402H16]  132.82 1.57 90 top
PR4468  100KR2J-1-GP  [R402H16]  174.44 9.24 180 top
PR4469  0R2F-1-GP  [R402H16]  171.75 10.73 0 top
PR4470  0R2F-1-GP  [R402H16]  138.64 2.12 90 top
PR4471  -  [0R0402-PAD]  137.51 3.55 270 top
PR4472  100KR2F-L3-GP  [R402H16]  151.47 21.82 90 bottom
PR4482  1R2F-GP  [R402H16]  151.77 19.85 270 bottom
PR4483  100R2F-L1-GP-U  [R402H14]  139.1 6.66 270 top
PR4485  0R0402-PAD-1-GP  [0R0402-PAD]  146.42 21.77 0 bottom
PR4486  0R0402-PAD-1-GP  [0R0402-PAD]  147.27 19.06 90 top
PR4487  0R0402-PAD-1-GP  [0R0402-PAD]  143.35 23.09 270 bottom
PR4488  0R0402-PAD-1-GP  [0R0402-PAD]  155.71 14.07 90 bottom
PR4489  0R0402-PAD-1-GP  [0R0402-PAD]  155.7 13.29 90 bottom
PR4490  0R0402-PAD-1-GP  [0R0402-PAD]  143.31 3.75 270 top
PR4491  0R0402-PAD-1-GP  [0R0402-PAD]  144.3 5.84 270 top
PR4492  0R0402-PAD-1-GP  [0R0402-PAD]  141.79 6.44 270 top
PR4494  0R0402-PAD-1-GP  [0R0402-PAD]  150.29 24.75 90 bottom
PR4496  0R0402-PAD-1-GP  [0R0402-PAD]  154.15 24.21 270 bottom
PR4497  0R0402-PAD-1-GP  [0R0402-PAD]  153.17 24.99 90 bottom
PR4498  0R0402-PAD-1-GP  [0R0402-PAD]  147.88 2 270 bottom
PR4501  0R0603-PAD-1-GP-U  [0R0603-PAD-U]  91.38 3.69 270 top
PR4502  348KR2F-GP  [R402H16]  79.07 2.13 0 top
PR4505  100KR2J-1-GP  [R402H16]  86.04 8.44 0 top
PR4506  1KR2F-3-GP  [R402H16]  87.47 11.66 0 bottom
PR4508  499KR2F-1-GP  [R402H16]  84.27 10.29 0 bottom
PR4509  499KR2F-1-GP  [R402H16]  83.45 7.97 270 bottom
PR4514  1MR2J-1-GP  [R402H16]  85.07 10.27 0 bottom
PR4552  100KR2J-1-GP  [R402H16]  80.78 4.77 270 top
PR4554  0R0603-PAD-1-GP-U  [0R0603-PAD-U]  72.61 9.34 90 bottom
PR4555  1KR2F-3-GP  [R402H16]  77.09 1.95 90 top
PR4556  1MR2J-1-GP  [R402H16]  79.86 2.26 0 top
PR4557  499KR2F-1-GP  [R402H16]  80.51 4.39 90 bottom
PR4558  499KR2F-1-GP  [R402H16]  78.89 5.07 180 top
PR4603  1KR2F-3-GP  [R402H16]  49.21 69.43 180 top
PR4604  100R2F-L1-GP-U  [R402H14]  46.8 69.45 180 top
PR4605  75R2F-2-GP  [R402H16]  47.61 69.45 180 top
PR4606  45D3R2F-L-GP  [R402H16]  48.4 69.43 180 top
PR4607  100R2F-L1-GP-U  [R402H14]  49.24 69.47 180 bottom
PR4608  100KR2F-L3-GP  [R402H16]  48.65 66.65 90 top
PR4609  10KR2F-2-GP  [R402H16]  50 69.47 180 bottom
PR4610  1R2J-GP  [R402H16]  45.25 69.55 180 bottom
PR4611  NTC-10K-29-GP-U  [NTC-402H22-U]  98.04 78.38 180 bottom
PR4612  0R0402-PAD-1-GP  [0R0402-PAD]  44.08 68.52 90 top
PR4613  -  [0R0402-PAD]  38.99 67.96 180 bottom
PR4614  0R2J-L-GP  [R402H15]  50.15 67.49 0 bottom
PR4615  1KR2F-3-GP  [R402H16]  41.87 68.59 0 bottom
PR4616  15KR2F-GP  [R402H16]  52.01 65.56 90 bottom
PR4617  NTC-470K-17-GP  [NTC-402H22-U]  71.9 87.4 270 bottom
PR4618  11KR2F-L-GP  [R402H16]  40.96 66.05 0 bottom
PR4620  430R2F-GP  [R402H16]  42.28 67.39 270 bottom
PR4621  27K4R2F-GP  [R402H16]  52.44 66.81 180 bottom
PR4622  10R2F-L1-GP  [R402H16]  46.85 69.5 180 bottom
PR4623  0R0402-PAD-1-GP  [0R0402-PAD]  47.64 69.52 180 bottom
PR4624  49D9R2F-GP  [R402H16]  48.43 69.47 180 bottom
PR4625  2K61R2F-1-GP  [R402H16]  39.71 65.79 90 bottom
PR4626  3K3R2F-2-GP  [R402H16]  52.72 64.37 90 bottom
PR4627  100R2F-L1-GP-U  [R402H14]  40.96 64.43 180 bottom
PR4628  9K31R2F-GP  [R402H16]  43.5 68.74 0 bottom
PR4629  100KR2F-L3-GP  [R402H16]  44.34 68.74 0 bottom
PR4630  2KR2F-L1-GP  [R402H16]  52.03 61.93 90 bottom
PR4631  100R2F-L1-GP-U  [R402H14]  55.61 60.29 270 bottom
PR4632  301R2F-GP  [R402H16]  41.41 63.25 270 bottom
PR4633  2K55R2F-GP  [R402H16]  52.03 61.13 90 bottom
PR4635  1KR2F-3-GP  [R402H16]  48.77 58.13 0 top
PR4636  499R2F-2-GP  [R402H16]  52.03 60.37 90 bottom
PR4637  1K78R2F-GP  [R402H16]  40.15 62.48 90 bottom
PR4638  2KR2F-L1-GP  [R402H16]  41.25 61.24 270 bottom
PR4640  2K49R2F-2-L-GP  [R402H16]  41.42 60.42 90 bottom
PR4641  2K61R2F-1-GP  [R402H16]  55.64 57.25 180 bottom
PR4642  536R2F-1-GP  [R402H16]  49.52 58.32 180 bottom
PR4643  11KR2F-L-GP  [R402H16]  51.3 58.5 90 bottom
PR4644  40K2R2F-GP  [R402H16]  44.46 63.99 90 top
PR4645  1KR2F-3-GP  [R402H16]  48.73 58.32 180 bottom
PR4646  NTC-10K-29-GP-U  [NTC-402H22-U]  70.18 73.63 90 bottom
PR4647  0R0402-PAD-1-GP  [0R0402-PAD]  50.63 56.95 270 bottom
PR4648  365R2F-GP  [R402H16]  40.85 62.94 270 top
PR4649  0R0402-PAD-1-GP  [0R0402-PAD]  40.02 59.82 180 top
PR4650  NTC-10K-29-GP-U  [NTC-402H22-U]  49.47 44.19 90 bottom
PR4651  1KR2F-3-GP  [R402H16]  39.86 61.9 270 top
PR4652  11KR2F-L-GP  [R402H16]  41.64 61.07 270 top
PR4653  2K61R2F-1-GP  [R402H16]  42.63 59.85 180 bottom
PR4654  NTC-470K-17-GP  [NTC-402H22-U]  36.74 47.53 90 bottom
PR4655  23K2R2F-GP  [R402H16]  45.99 58.63 90 top
PR4656  2K87R2F-1-GP  [R402H16]  45.63 62.41 270 top
PR4657  2KR2F-L1-GP  [R402H16]  47.08 59.8 180 bottom
PR4658  499R2F-2-GP  [R402H16]  46.32 59.8 180 bottom
PR4659  100R2F-L1-GP-U  [R402H14]  43.85 59.47 90 bottom
PR4660  1K91R2F-1-GP  [R402H16]  45.55 59.8 180 bottom
PR4661  84K5R2F-GP  [R402H16]  48.45 62.79 180 top
PR4662  9K53R2F-GP  [R402H16]  46.19 59.82 0 top
PR4665  0R0402-PAD-1-GP  [0R0402-PAD]  54.41 59.3 90 bottom
PR4666  0R0402-PAD-1-GP  [0R0402-PAD]  54.42 58.53 90 bottom
PR4669  0R2J-L-GP  [R402H15]  48.88 60.25 270 bottom
PR4685  100R2F-L1-GP-U  [R402H14]  48.68 64.27 270 top
PR4686  100R2F-L1-GP-U  [R402H14]  45 60.28 270 top
PR4692  0R0402-PAD-1-GP  [0R0402-PAD]  38.93 64.95 90 bottom
PR4693  0R0402-PAD-1-GP  [0R0402-PAD]  38.37 63.63 0 bottom
PR4694  0R0402-PAD-1-GP  [0R0402-PAD]  42.94 59.87 180 top
PR4695  0R0402-PAD-1-GP  [0R0402-PAD]  43.75 59.85 180 top
PR4702  0R0402-PAD-1-GP  [0R0402-PAD]  64.97 86.7 270 bottom
PR4703  2D2R2F-GP  [R402H16]  67.27 86.43 180 top
PR4704  2D2R3F-L-GP  [R603H24]  72.27 85.92 270 top
PR4705  2D2R6J-3-GP  [R1206H28]  68.16 78.8 180 top
PR4706  0R0402-PAD-1-GP  [0R0402-PAD]  67.84 88.09 270 bottom
PR4708  3K65R2F-1-GP  [R402H16]  50.84 59.34 90 bottom
PR4709  10R2F-L1-GP  [R402H16]  47.94 57.61 0 bottom
PR4710  2D2R3F-L-GP  [R603H24]  93.65 86.9 270 top
PR4711  0R0402-PAD-1-GP  [0R0402-PAD]  86.67 87.02 90 top
PR4712  0R0402-PAD-1-GP  [0R0402-PAD]  90.03 86.32 180 top
PR4713  2D2R2F-GP  [R402H16]  86.83 86.16 0 bottom
PR4714  2D2R6J-3-GP  [R1206H28]  91.66 78.92 180 top
PR4715  10R2F-L1-GP  [R402H16]  51.03 57.93 90 top
PR4716  3K65R2F-1-GP  [R402H16]  51.36 59.64 0 top
PR4717  5K11R2F-L1-GP  [R402H16]  64.89 87.52 90 bottom
PR4718  5K11R2F-L1-GP  [R402H16]  88.51 86.17 0 top
PR4721  100KR2F-L3-GP  [R402H16]  49.95 61.6 90 top
PR4722  100KR2F-L3-GP  [R402H16]  47.16 59.08 0 top
PR4723  100KR2F-L3-GP  [R402H16]  50.08 59.31 90 top
PR4724  100KR2F-L3-GP  [R402H16]  51.03 57.17 90 top
PR4801  0R0402-PAD-1-GP  [0R0402-PAD]  48.54 54.13 180 top
PR4802  0R0402-PAD-1-GP  [0R0402-PAD]  41.6 46.84 0 top
PR4803  2D2R6J-3-GP  [R1206H28]  46.76 50.33 180 top
PR4804  2D2R2F-GP  [R402H16]  39.06 46.9 180 bottom
PR4805  2D2R3F-L-GP  [R603H24]  43.41 47.45 180 top
PR4806  0R0402-PAD-1-GP  [0R0402-PAD]  40.73 46.89 0 top
PR4808  3K65R2F-1-GP  [R402H16]  47.66 54.13 180 top
PR4812  5K11R2F-L1-GP  [R402H16]  41.76 46.89 180 bottom
PR5001  2D2R3F-L-GP  [R603H24]  106.01 87.91 180 top
PR5003  3K65R2F-1-GP  [R402H16]  40.25 67.62 270 bottom
PR5004  0R0402-PAD-1-GP  [0R0402-PAD]  36.39 64.9 270 bottom
PR5101  10R2J-L-GP  [R402H16]  30.39 43.72 270 bottom
PR5102  6K49R2F-1-GP  [R402H16]  32.05 43.77 270 bottom
PR5104  100KR2J-1-GP  [R402H16]  28.84 42.94 270 bottom
PR5105  6K2R2F-GP  [R402H16]  29.74 39.73 0 bottom
PR5106  10K2R2F-GP  [R402H16]  28.43 40.19 90 bottom
PR5107  -  [0R0402-PAD]  26.5 40.81 0 bottom
PR5108  510KR2F-GP  [R402H16]  28.84 42.18 270 bottom
PR5110  2D2R5J-1-GP  [R805H24]  34.77 42.11 180 top
PR5111  0R0805-PAD-1-GP-U  [0R0805-PAD-U]  37 36.63 90 top
PR5151  47KR2J-2-GP  [R402H16]  28.38 35.01 0 bottom
PR5152  10KR2F-2-GP  [R402H16]  27.83 33.05 270 bottom
PR5153  0R0402-PAD-1-GP  [0R0402-PAD]  27.77 33.81 270 bottom
PR5154  18KR2F-GP  [R402H16]  37.58 31.88 180 top
PR5155  14K3R2F-GP  [R402H16]  36.82 33.43 180 top
PR5156  1MR2J-1-GP  [R402H16]  27.42 32.02 90 bottom
PR5201  95K3R2F-GP  [R402H16]  127.12 86.15 90 bottom
PR5202  3K16R2F-GP  [R402H16]  127.12 88.57 90 bottom
PR5203  100KR2F-L3-GP  [R402H16]  125.03 87.15 0 bottom
PR5204  10KR2F-2-GP  [R402H16]  126.22 87.79 90 bottom
PR5208  100KR2J-1-GP  [R402H16]  124.22 87.25 0 top
PR5210  47KR2F-GP  [R402H16]  123.47 87.23 180 bottom
PR5304  49K9R2F-L-GP  [R402H16]  26.73 45.19 0 bottom
PR5305  100KR2F-L3-GP  [R402H16]  27.61 44.75 180 bottom
PR5306  100KR2F-L3-GP  [R402H16]  23.96 44.91 0 bottom
PR5307  -  [0R0805-PAD]  30.4 46.03 270 bottom
PR5310  -  [0R0402-PAD]  27.46 47.88 0 top
PR5311  -  [0R0402-PAD]  24.74 44.86 0 bottom
PR8510  -  [0R0402-PAD]  149.76 26.37 270 top
PR8517  -  [0R0402-PAD]  143.47 24.96 90 bottom
PR8520  -  [0R0402-PAD]  144.7 25.33 0 bottom
PR8522  -  [0R0402-PAD]  149.04 28.99 0 top
PR8551  2D2R3F-L-GP  [R603H24]  149.5 29.76 270 bottom
PR8556  2D2R3F-L-GP  [R603H24]  145.67 32.14 90 bottom
PR8557  10KR2J-L-GP  [R402H15]  146.81 85.21 0 top
PR8559  49K9R2F-L-GP  [R402H16]  148.85 27.74 270 top
PR8561  2D2R3F-L-GP  [R603H24]  142.45 25.2 90 top
PR8562  499KR2F-1-GP  [R402H16]  144.03 25.09 180 top
PR8563  16K5R2F-2-GP  [R402H16]  146.49 28.02 270 top
PR8564  147KR2F-GP  [R402H16]  141.25 28.79 90 bottom
PR8566  20K5R2F-GP  [R402H16]  146.37 25.35 180 bottom
PR8567  6K19R2F-GP  [R402H16]  147.95 25.33 0 bottom
PR8568  4K32R2F-GP  [R402H16]  147.17 25.36 0 bottom
PR8569  100R2F-L1-GP-U  [R402H14]  142.84 26.19 270 top
PR8570  16K5R2F-2-GP  [R402H16]  147.29 25.81 270 top
PR8571  0R2J-L-GP  [R402H15]  141.38 27.48 90 bottom
PR8572  309R2F-GP  [R402H16]  146.06 25.38 0 top
PR8573  2D2R3F-L-GP  [R603H24]  141.36 29.8 90 bottom
PR8577  100R2F-L1-GP-U  [R402H14]  141.38 26.71 90 bottom
PR8611  100KR2F-L3-GP  [R402H16]  175.33 33.89 270 bottom
PR8612  100KR2F-L3-GP  [R402H16]  133.64 76.93 90 bottom
PR8613  34K8R2F-1-GP  [R402H16]  139.57 87.51 270 bottom
PR8614  49K9R2F-L-GP  [R402H16]  132.37 77.2 180 bottom
PR8620  51KR2F-L-GP  [R402H16]  140.76 88.18 0 bottom
PR8621  -  [0R0402-PAD]  152.23 81.14 315 top
PR8623  -  [0R0402-PAD]  144.39 83.84 0 top
PR8624  10KR2J-L-GP  [R402H15]  130.11 77.88 270 bottom
PR8625  10KR2J-L-GP  [R402H15]  145.04 85.89 270 top
PR8626  12KR2F-L-GP  [R402H16]  177.72 36.25 90 top
PR8627  15KR2F-GP  [R402H16]  175.31 36.23 270 bottom
PR8630  -  [0R0402-PAD]  175.33 34.66 270 bottom
PR8631  -  [0R0402-PAD]  175.33 35.44 270 bottom
PR8632  0R2J-L-GP  [R402H15]  178.65 35.04 90 top
PR8633  -  [0R0603-PAD]  183.06 37.47 270 bottom
PR8634  -  [0R0402-PAD]  177.78 37.82 270 top
PR8650  10KR2J-L-GP  [R402H15]  127.96 67.79 90 bottom
PT4701  SE330U2VDM-4-GP  [CT7343H83]  81.74 77.21 0 bottom
PT4703  SE330U2VDM-4-GP  [CT7343H83]  76.94 77.19 0 bottom
PT4801  SE330U2VDM-4-GP  [CT7343H83]  49.11 54.14 90 bottom
PT8553  SE330U2VDM-4-GP  [CT7343H83]  144.93 43.02 180 bottom
PT8555  SE330U2VDM-4-GP  [CT7343H83]  132.95 43.26 180 bottom
PU44A1  AS331KTR-G1-GP  [SOT-23-5H58]  153.66 27.18 0 bottom
PU44B1  AS331KTR-G1-GP  [SOT-23-5H58]  153.88 30.79 180 bottom
PU44C1  AP2204K-ADJTRG1-GP  [SOT-23-5H58]  157.29 30.01 0 bottom
PU4301  AONR21321-GP  [PPAK-8P-3232H36]  29.39 76.18 90 top
PU4401  ISL9538HRTZ-GP-U  [QFN32J4-G2D85H34]  151.05 14.28 270 bottom
PU4402  FDMS3600-02-RJK0215-COLAY-GP  [PPAK-8P-G5324H44-COLAY]  135.26 11.88 0 top
PU4403  FDMS3600-02-RJK0215-COLAY-GP  [PPAK-8P-G5324H44-COLAY]  131.87 18.26 270 top
PU4412  SM3305PSQAC-TRG-GP  [PPAK-8P-3232H40]  120.49 8.88 0 bottom
PU4415  AONR21321-GP  [PPAK-8P-3232H36]  29.95 72.96 0 top
PU4501  SY8288BRAC-GP  [QFN20Z3-G1D1H36]  87.17 6.45 0 bottom
PU4551  SY8288CRAC-GP  [QFN20Z3-G1D1H36]  77.71 6 180 bottom
PU4601  ISL95859CHRTZ-T-1-GP  [QFN40J5-G3D6-DIFF-H34]  46.57 64.88 90 bottom
PU4701  AOZ5038QI-05-GP  [QFN31G5-G4P-9H34]  69.52 84.1 180 bottom
PU4702  AOZ5038QI-05-GP  [QFN31G5-G4P-9H34]  90.42 84.43 180 bottom
PU4801  AOZ5038QI-05-GP  [QFN31G5-G4P-9H34]  41.28 51.08 270 bottom
PU5001  AON7408-GP  [PPAK-8P-3232H36]  99.78 82.46 0 top
PU5002  ISL95808HRZ-T-1-GP  [DFN8G2-G1710-U1H40]  103.74 86.47 0 top
PU5003  AON7408-GP  [PPAK-8P-3232H36]  103.59 81.19 180 top
PU5101  APW8861QBI-TRG-GP-U  [QFN32J4-G3P-1UH32]  33.62 40.95 270 bottom
PU5151  APL5934KAI-TRG-GP-U  [SOIC8-G3530H63]  32.22 31.93 270 bottom
PU5201  AOZ2262QI-10-2-GP  [QFN22G4-G2PH42]  125.46 83.27 180 bottom
